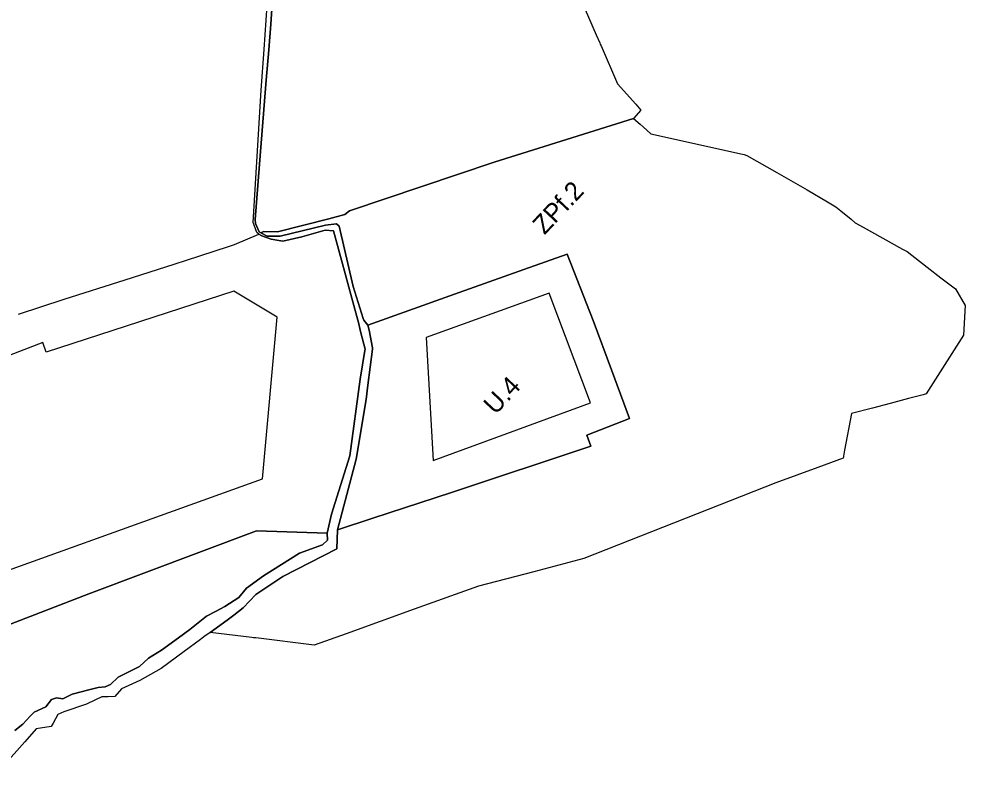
# Model space of a CAD drawing. Extents: x 7425782 to 7428854, y 5550411 to 5553074.
# Drawn here: x 7427625.3 to 7428082.7, y 5551811.2 to 5552172.4 of the extents above; entities that cross this region are included whole.
import ezdxf

# ---------------------------------------------------------------- set-up
doc = ezdxf.new("R2010")
doc.units = 0
for name, color, linetype in [('LIN_linie_rozgraniczajace', 7, 'Continuous'), ('LIN_nieprzekraczalna linia zabudowy', 7, 'Continuous'), ('TXT_oznaczenia przeznaczen', 7, 'Continuous')]:
    doc.layers.add(name, color=color, linetype=linetype)

msp = doc.modelspace()

# ---------------------------------------------------------------- linework, layer by layer
at = {"layer": 'LIN_linie_rozgraniczajace'}
for points in [[(7427748.12, 5552186.94), (7427747.07, 5552169.79), (7427746.18, 5552157.44), (7427744.78, 5552142.83), (7427741.6, 5552102.13), (7427739.53, 5552075.49), (7427739.68, 5552073.49), (7427741.41, 5552069.49), (7427742.48, 5552068.85), (7427745.33, 5552067.42), (7427751.57, 5552067.34), (7427773.46, 5552072.75), (7427778.79, 5552073.33), (7427780.1, 5552072.23), (7427786.95, 5552043.11), (7427791.77, 5552027.57), (7427791.96, 5552026.74), (7427793.95, 5552024.28), (7427794.59, 5552021.88), (7427796.27, 5552013.34), (7427796.19, 5552012.73), (7427793.98, 5551995.38), (7427793.08, 5551988.36), (7427788.27, 5551959.66), (7427779.28, 5551925.5), (7427779.03, 5551916.26), (7427752.92, 5551902.81), (7427739.77, 5551894.13), (7427733.64, 5551887.78), (7427729.24, 5551884.24), (7427725.92, 5551881.84), (7427717.7, 5551875.86), (7427714.75, 5551873.68), (7427712.99, 5551872.37), (7427705.11, 5551866.56), (7427694.1, 5551858.43), (7427683.74, 5551852.54), (7427683.74, 5551852.54), (7427674.93, 5551848.63), (7427671.65, 5551844.81), (7427671.65, 5551844.81), (7427668.49, 5551844.74), (7427665.37, 5551844.68), (7427662.25, 5551843.24), (7427657.89, 5551841.23), (7427646.92, 5551837.47), (7427646.92, 5551837.47), (7427644.03, 5551836.22), (7427641.83, 5551832.03), (7427640.93, 5551830.31), (7427633.58, 5551829.18), (7427633.58, 5551829.18), (7427628.07, 5551822.99), (7427617.6, 5551811.23)], [(7427896.99, 5552181.92), (7427904.38, 5552164.78), (7427906.07, 5552160.88), (7427906.34, 5552160.25), (7427906.74, 5552159.34), (7427914.62, 5552140.95), (7427914.62, 5552140.95), (7427923.48, 5552131.11), (7427923.48, 5552131.11), (7427926.01, 5552128.31), (7427922.4, 5552124.33), (7427922.4, 5552124.33), (7427854.99, 5552103.22), (7427785.06, 5552079.67), (7427782.86, 5552077.79), (7427775.15, 5552075.82), (7427750.35, 5552069.47), (7427743.63, 5552069.58), (7427742.84, 5552069.32), (7427742.48, 5552068.85), (7427741.41, 5552069.49), (7427739.68, 5552073.49), (7427739.53, 5552075.49), (7427741.6, 5552102.13), (7427744.78, 5552142.83), (7427746.18, 5552157.44), (7427747.07, 5552169.79), (7427748.12, 5552186.94)], [(7427623.33, 5551828.36), (7427627.12, 5551831.5), (7427630.66, 5551835.35), (7427632.67, 5551837.33), (7427638.35, 5551839.93), (7427641.06, 5551843.37), (7427643.52, 5551844.22), (7427646.44, 5551843.73), (7427651.04, 5551845.98), (7427659, 5551848.02), (7427663.56, 5551849.29), (7427666.92, 5551849.49), (7427669.52, 5551850.71), (7427673.23, 5551854.17), (7427683.5, 5551859.4), (7427687.89, 5551863.35), (7427694.22, 5551867.3), (7427702.42, 5551873.17), (7427707.9, 5551877.27), (7427715.91, 5551883.65), (7427720.65, 5551886.13), (7427724.88, 5551888.39), (7427731.6, 5551892.69), (7427735.26, 5551897.2), (7427743.56, 5551903.23), (7427760.93, 5551914.1), (7427772.01, 5551918.16), (7427774.49, 5551920.37), (7427774.32, 5551923.82), (7427776.43, 5551933.07), (7427785.2, 5551961.24), (7427790.26, 5551998.2), (7427792.55, 5552012.08), (7427792.65, 5552012.73), (7427790.54, 5552020.69), (7427790.06, 5552022.78), (7427789.68, 5552025.05), (7427777.29, 5552070.03), (7427773.33, 5552070.36), (7427762.11, 5552067), (7427752.87, 5552064.91), (7427750.87, 5552065.35), (7427747.19, 5552065.86), (7427742.76, 5552067.48), (7427741.27, 5552068.39), (7427740.31, 5552069.14), (7427738.96, 5552072.64), (7427738.52, 5552074.04), (7427742.38, 5552137.92), (7427743.79, 5552157.59), (7427745.25, 5552178.93)], [(7427625.13, 5552029.74), (7427647.14, 5552036.9), (7427676.64, 5552046.2), (7427700.28, 5552053.78), (7427706.26, 5552055.72), (7427726.57, 5552062.31), (7427729.47, 5552063.29), (7427741.27, 5552068.39), (7427742.76, 5552067.48), (7427747.19, 5552065.86), (7427750.87, 5552065.35), (7427752.87, 5552064.91), (7427762.11, 5552067), (7427773.33, 5552070.36), (7427777.29, 5552070.03), (7427789.68, 5552025.05), (7427790.06, 5552022.78), (7427790.54, 5552020.69), (7427792.65, 5552012.73), (7427792.55, 5552012.08), (7427790.26, 5551998.2), (7427785.2, 5551961.24), (7427776.43, 5551933.07), (7427774.32, 5551923.82), (7427740.21, 5551924.89), (7427659.08, 5551894.5), (7427580.93, 5551864.35)], [(7427580.93, 5551864.35), (7427659.08, 5551894.5), (7427740.21, 5551924.89), (7427774.32, 5551923.82), (7427774.49, 5551920.37), (7427772.01, 5551918.16), (7427760.93, 5551914.1), (7427743.56, 5551903.23), (7427735.26, 5551897.2), (7427731.6, 5551892.69), (7427724.88, 5551888.39), (7427720.65, 5551886.13), (7427715.91, 5551883.65), (7427707.9, 5551877.27), (7427702.42, 5551873.17), (7427694.22, 5551867.3), (7427687.89, 5551863.35), (7427683.5, 5551859.4), (7427673.23, 5551854.17), (7427669.52, 5551850.71), (7427666.92, 5551849.49), (7427663.56, 5551849.29), (7427659, 5551848.02), (7427651.04, 5551845.98), (7427646.44, 5551843.73), (7427643.52, 5551844.22), (7427641.06, 5551843.37), (7427638.35, 5551839.93), (7427632.67, 5551837.33), (7427630.66, 5551835.35), (7427627.12, 5551831.5), (7427623.33, 5551828.36)]]:
    msp.add_lwpolyline(points, dxfattribs=at)
for points in [[(7428029.65, 5552073.9), (7428033.42, 5552071.79), (7428052.48, 5552061.11), (7428054.66, 5552059.9), (7428064.44, 5552052.39), (7428071.08, 5552047.29), (7428078.16, 5552041.85), (7428082.73, 5552033.89), (7428081.91, 5552019.5), (7428063.85, 5551991.1), (7428062.46, 5551990.74), (7428055.41, 5551988.89), (7428046.57, 5551986.56), (7428037.94, 5551984.29), (7428027.83, 5551981.63), (7428024.47, 5551963.96), (7428023.96, 5551961.1), (7428023.88, 5551960.68), (7428023.76, 5551959.99), (7428011.57, 5551955.57), (7427991.24, 5551948.2), (7427898.43, 5551911.53), (7427874.2, 5551905.16), (7427847.47, 5551898.13), (7427816.37, 5551887), (7427783.47, 5551875.23), (7427768.04, 5551869.71), (7427739.86, 5551873.15), (7427738.67, 5551873.3), (7427737.95, 5551873.39), (7427717.7, 5551875.86), (7427725.92, 5551881.84), (7427729.24, 5551884.24), (7427733.64, 5551887.78), (7427739.77, 5551894.13), (7427752.92, 5551902.81), (7427779.03, 5551916.26), (7427779.28, 5551925.5), (7427796.4, 5551930.99), (7427834.37, 5551943.51), (7427901.72, 5551965.8), (7427899.87, 5551971.22), (7427920.46, 5551979.31), (7427911.78, 5552002.76), (7427902.94, 5552026.62), (7427890.33, 5552058.76), (7427869.42, 5552051.31), (7427835.81, 5552039.28), (7427793.95, 5552024.28), (7427791.96, 5552026.74), (7427791.77, 5552027.57), (7427786.95, 5552043.11), (7427780.1, 5552072.23), (7427778.79, 5552073.33), (7427773.46, 5552072.75), (7427751.57, 5552067.34), (7427745.33, 5552067.42), (7427742.48, 5552068.85), (7427742.84, 5552069.32), (7427743.63, 5552069.58), (7427750.35, 5552069.47), (7427775.15, 5552075.82), (7427782.86, 5552077.79), (7427785.06, 5552079.67), (7427854.99, 5552103.22), (7427922.4, 5552124.33), (7427925.69, 5552121.51), (7427925.69, 5552121.51), (7427927.02, 5552120.28), (7427930.73, 5552116.84), (7427975.05, 5552107.04), (7427975.85, 5552106.8), (7427977.15, 5552106.42), (7427991.67, 5552098.19), (7428006.38, 5552089.85), (7428016.23, 5552083.97), (7428020.21, 5552081.59), (7428022.67, 5552079.58), (7428027.66, 5552075.52), (7428029.65, 5552073.9)], [(7427779.28, 5551925.5), (7427788.27, 5551959.66), (7427793.08, 5551988.36), (7427793.98, 5551995.38), (7427796.19, 5552012.73), (7427796.27, 5552013.34), (7427794.59, 5552021.88), (7427793.95, 5552024.28), (7427835.81, 5552039.28), (7427869.42, 5552051.31), (7427890.33, 5552058.76), (7427902.94, 5552026.62), (7427911.78, 5552002.76), (7427920.46, 5551979.31), (7427899.87, 5551971.22), (7427901.72, 5551965.8), (7427834.37, 5551943.51), (7427796.4, 5551930.99)]]:
    msp.add_lwpolyline(points, close=True, dxfattribs=at)
at = {"layer": 'LIN_nieprzekraczalna linia zabudowy'}
for points in [[(7427362.07, 5551814.56), (7427402.21, 5551827.55), (7427743.05, 5551950.14), (7427750.05, 5552028.23), (7427729.2, 5552040.85)], [(7427729.2, 5552040.85), (7427638.52, 5552011.24), (7427636.88, 5552015.96), (7427583.69, 5551995.55), (7427519.59, 5551971.59), (7427492.84, 5551963.62), (7427468.35, 5551954.25), (7427473.77, 5551939.85), (7427477.77, 5551923.1), (7427470.24, 5551920.05), (7427472.36, 5551914.12)]]:
    msp.add_lwpolyline(points, dxfattribs=at)
msp.add_lwpolyline([(7427881.68, 5552039.76), (7427822.11, 5552018.44), (7427825.62, 5551958.96), (7427901.69, 5551986.77)], close=True, dxfattribs=at)

# ---------------------------------------------------------------- texts
at = {"layer": 'TXT_oznaczenia przeznaczen'}
for s, p in [('ZPf.2', (7427879.37, 5552067.7)), ('U.4', (7427855.63, 5551980.67))]:
    msp.add_text(s, height=9, rotation=46.7736, dxfattribs=at).set_placement(p)

doc.saveas('drawing.dxf')
